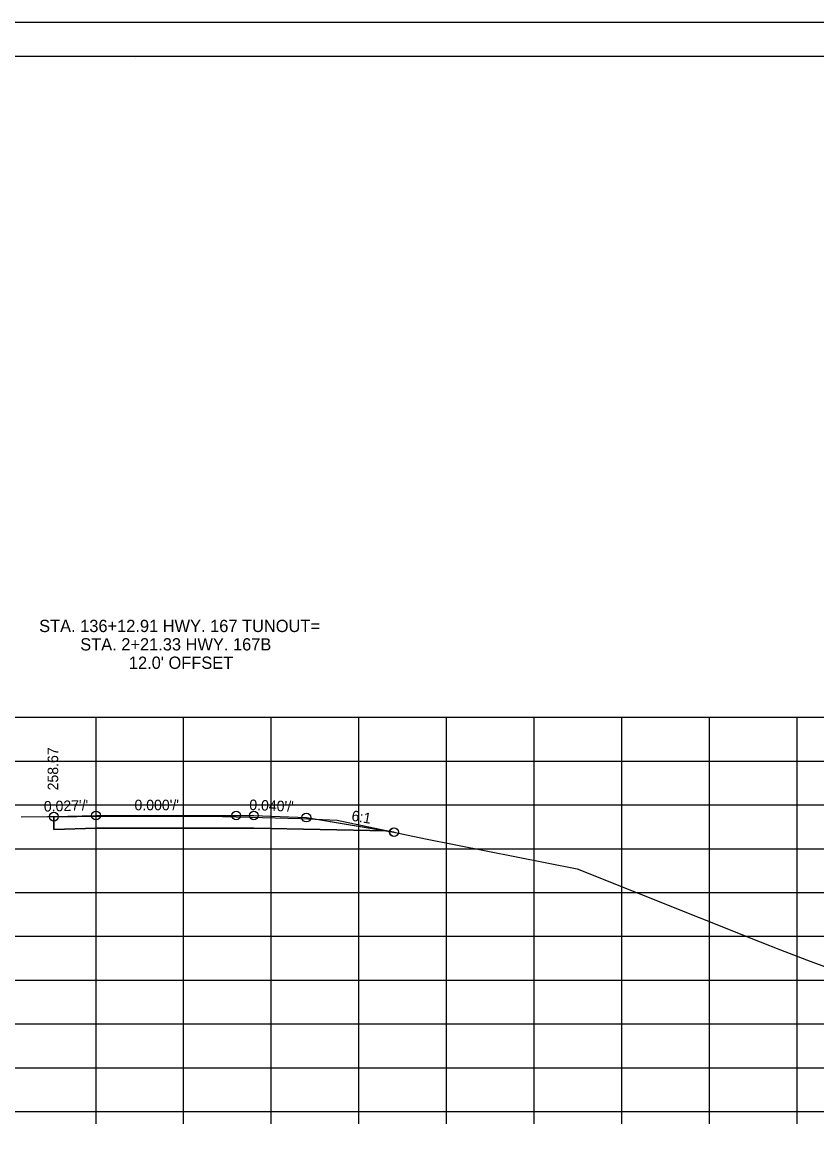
# Model space of a CAD drawing. Extents: x 1103485 to 1107180, y 2010593 to 2011873.
# Drawn here: x 1106998.8 to 1107089.4, y 2011746.4 to 2011872.9 of the extents above; entities that cross this region are included whole.
import ezdxf

# ---------------------------------------------------------------- set-up
doc = ezdxf.new("R2010")
doc.units = 0
for name, color, linetype in [('R_Alt Surface', 7, 'Continuous'), ('R_Axis', 7, 'Continuous'), ('R_Axis Annot', 7, 'Continuous'), ('R_Border', 7, 'Continuous'), ('R_Contours', 7, 'Continuous'), ('R_Exist Surface', 7, 'Continuous'), ('R_Fin Surface', 7, 'Continuous'), ('R_Grid', 7, 'Continuous'), ('R_No Plot', 7, 'Continuous'), ('R_Proposed Const Limits', 7, 'Continuous'), ('R_Xsect Elev', 7, 'Continuous'), ('R_Xsect Slope', 7, 'Continuous')]:
    doc.layers.add(name, color=color, linetype=linetype)

msp = doc.modelspace()

# ---------------------------------------------------------------- linework, layer by layer
at = {"layer": 'R_Alt Surface'}
msp.add_lwpolyline([(1107002.36, 2011782.17), (1107002.36, 2011780.71), (1107007.18, 2011780.84), (1107025.18, 2011780.84), (1107040.32, 2011780.54)], dxfattribs=at)
at = {"layer": 'R_Axis'}
for p, q in [((1106867.18, 2011748.51), (1107167.18, 2011748.51)), ((1107007.18, 2011747.11), (1107007.18, 2011748.51)), ((1107017.18, 2011747.11), (1107017.18, 2011748.51)), ((1107027.18, 2011747.11), (1107027.18, 2011748.51)), ((1107037.18, 2011747.11), (1107037.18, 2011748.51)), ((1107047.18, 2011747.11), (1107047.18, 2011748.51)), ((1107057.18, 2011747.11), (1107057.18, 2011748.51)), ((1107067.18, 2011747.11), (1107067.18, 2011748.51)), ((1107077.18, 2011747.11), (1107077.18, 2011748.51)), ((1107087.18, 2011747.11), (1107087.18, 2011748.51))]:
    msp.add_line(p, q, dxfattribs=at)
at = {"layer": 'R_Border'}
for p, q in [((1106859.18, 2011868.97), (1107175.36, 2011868.97)), ((1107011.7, 2011868.71), (1107011.7, 2011868.71)), ((1107011.7, 2011868.71), (1107011.7, 2011868.71))]:
    msp.add_line(p, q, dxfattribs=at)
at = {"layer": 'R_Contours'}
msp.add_lwpolyline([(1107002.36, 2011782.17), (1107004.98, 2011782.18), (1107017.87, 2011782.24), (1107021.63, 2011782.18), (1107024.75, 2011782.12), (1107030.5, 2011781.94), (1107034.7, 2011781.77), (1107041.2, 2011780.4), (1107041.18, 2011780.4), (1107040.32, 2011780.54), (1107025.18, 2011780.84), (1107007.18, 2011780.84), (1107002.36, 2011780.71)], close=True, dxfattribs=at)
at = {"layer": 'R_Exist Surface'}
msp.add_lwpolyline([(1106998.64, 2011782.16), (1107001.63, 2011782.17), (1107004.98, 2011782.18), (1107017.87, 2011782.24), (1107021.63, 2011782.18), (1107024.75, 2011782.12), (1107030.5, 2011781.94), (1107034.7, 2011781.77), (1107044.78, 2011779.65), (1107062.07, 2011776.22), (1107082.97, 2011767.89), (1107085.3, 2011766.95), (1107088.27, 2011765.84), (1107092.79, 2011764.16), (1107094.49, 2011763.68), (1107105.87, 2011759.98), (1107107.21, 2011760.21), (1107121.37, 2011763.28)], dxfattribs=at)
at = {"layer": 'R_Fin Surface'}
for points in [[(1107002.36, 2011782.17), (1107007.18, 2011782.3), (1107007.18, 2011782.3), (1107023.18, 2011782.3), (1107025.18, 2011782.3), (1107031.18, 2011782.06), (1107040.32, 2011780.54), (1107041.18, 2011780.4), (1107041.2, 2011780.4)], [(1107002.36, 2011782.17), (1107007.18, 2011782.3), (1107023.18, 2011782.3), (1107025.18, 2011782.3), (1107031.18, 2011782.06)]]:
    msp.add_lwpolyline(points, dxfattribs=at)
at = {"layer": 'R_Grid'}
for p, q in [((1106867.18, 2011793.51), (1107167.18, 2011793.51)), ((1107007.18, 2011748.51), (1107007.18, 2011793.51)), ((1107017.18, 2011748.51), (1107017.18, 2011793.51)), ((1107027.18, 2011748.51), (1107027.18, 2011793.51)), ((1107037.18, 2011748.51), (1107037.18, 2011793.51)), ((1107047.18, 2011748.51), (1107047.18, 2011793.51)), ((1107057.18, 2011748.51), (1107057.18, 2011793.51)), ((1107067.18, 2011748.51), (1107067.18, 2011793.51)), ((1107077.18, 2011748.51), (1107077.18, 2011793.51)), ((1107087.18, 2011748.51), (1107087.18, 2011793.51)), ((1106867.18, 2011788.51), (1107167.18, 2011788.51)), ((1106867.18, 2011783.51), (1107167.18, 2011783.51)), ((1106867.18, 2011778.51), (1107167.18, 2011778.51)), ((1106867.18, 2011773.51), (1107167.18, 2011773.51)), ((1106867.18, 2011768.51), (1107167.18, 2011768.51)), ((1106867.18, 2011763.51), (1107167.18, 2011763.51)), ((1106867.18, 2011758.51), (1107167.18, 2011758.51)), ((1106867.18, 2011753.51), (1107167.18, 2011753.51)), ((1106867.18, 2011748.51), (1107167.18, 2011748.51))]:
    msp.add_line(p, q, dxfattribs=at)
at = {"layer": 'R_No Plot'}
msp.add_line((1106846.78, 2011872.86), (1107180.12, 2011872.86), dxfattribs=at)
for points in [[(1106846.78, 2011872.86), (1107180.12, 2011872.86), (1107180.12, 2011659.52), (1106846.78, 2011659.52)], [(1107093.1, 2011868.97), (1107093.1, 2011859.09), (1107128.84, 2011859.09), (1107128.84, 2011856.17), (1107152.04, 2011856.17), (1107152.04, 2011831.83), (1107175.36, 2011831.83), (1107175.36, 2011663.51), (1106859.18, 2011663.51), (1106859.18, 2011868.97)]]:
    msp.add_lwpolyline(points, close=True, dxfattribs=at)
for centre in [(1107002.36, 2011782.17), (1107007.18, 2011782.3), (1107023.18, 2011782.3), (1107025.18, 2011782.3), (1107031.18, 2011782.06), (1107041.18, 2011780.4), (1107041.2, 2011780.4)]:
    msp.add_circle(centre, 0.5, dxfattribs=at)
at = {"layer": 'R_Proposed Const Limits'}
msp.add_lwpolyline([(1107031.18, 2011782.06), (1107041.18, 2011780.4), (1107041.2, 2011780.4)], dxfattribs=at)

# ---------------------------------------------------------------- texts
at = {"layer": 'R_Axis Annot'}
for s, p in [('STA. 136+12.91 HWY. 167 TUNOUT=', (1107000.69, 2011803.24)), ('STA. 2+21.33 HWY. 167B', (1107005.38, 2011801.14)), ("12.0' OFFSET", (1107010.93, 2011799.04))]:
    msp.add_text(s, height=1.4, dxfattribs=at).set_placement(p)
at = {"layer": 'R_Xsect Elev'}
msp.add_text('258.67', height=1.2, rotation=90, dxfattribs=at).set_placement((1107002.86, 2011785.17))
at = {"layer": 'R_Xsect Slope'}
for s, rotation, p in [("0.027'/'", 1.5466, (1107001.24, 2011782.74)), ("0.000'/'", 359.9995, (1107011.57, 2011782.9)), ("0.040'/'", 357.7094, (1107024.65, 2011782.93)), ('6:1', 350.5358, (1107036.27, 2011781.72))]:
    msp.add_text(s, height=1.2, rotation=rotation, dxfattribs=at).set_placement(p)

doc.saveas('drawing.dxf')
